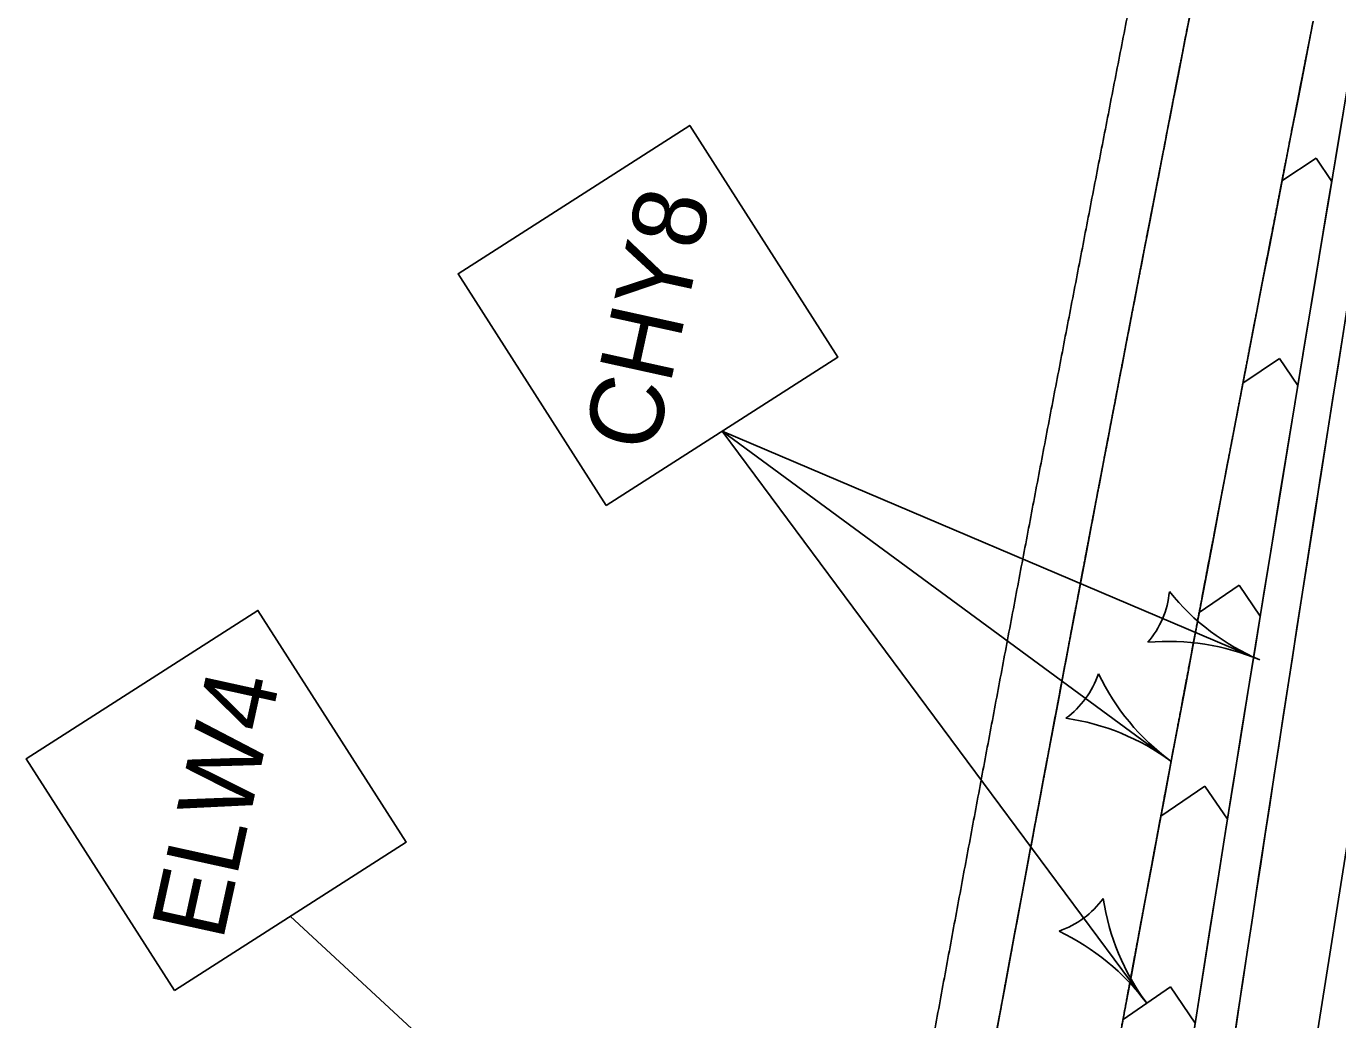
# Model space of a CAD drawing. Extents: x 14104283 to 14128447, y 8633203 to 8671666.
# Drawn here: x 14107883.7 to 14108012.5, y 8640340.4 to 8640438 of the extents above; entities that cross this region are included whole.
import ezdxf

# ---------------------------------------------------------------- set-up
doc = ezdxf.new("R2010")
doc.units = 0
for name, color, linetype in [('Default', 7, 'Continuous'), ('dsnPaintPlaceBrokenLineWhite', 7, 'Continuous'), ('dsnPaintPlaceChannelizingLaneWhite', 7, 'Continuous'), ('dsnPaintPlaceEdgeLineRightWhite', 7, 'Continuous'), ('dsnStdLabel', 7, 'Continuous'), ('dsnStgShadingPrevPav', 7, 'Continuous')]:
    doc.layers.add(name, color=color, linetype=linetype)

msp = doc.modelspace()

# ---------------------------------------------------------------- linework, layer by layer
at = {"layer": 'Default'}
for centre, radius, start, end in [((14117394.14, 8638857.08), 9512, 167.610212, 171.325989), ((14117394.14, 8638857.08), 9500, 167.610212, 171.325989), ((14117394.14, 8638857.08), 9500, 167.610212, 171.325989), ((14117350.61, 8638608.07), 9530.2, 168.915826, 170.320937), ((14117350.61, 8638608.07), 9518.2, 168.915826, 170.320937)]:
    msp.add_arc(centre, radius, start, end, dxfattribs=at)
at = {"layer": 'dsnPaintPlaceBrokenLineWhite'}
msp.add_arc((14117394.14, 8638857.08), 9500, 167.610212, 171.325989, dxfattribs=at)
at = {"layer": 'dsnPaintPlaceChannelizingLaneWhite'}
for p, q in [((14108006.99, 8640422.76), (14108010.34, 8640425.01)), ((14108011.88, 8640422.72), (14108010.34, 8640425.01)), ((14108003.16, 8640402.9), (14108006.75, 8640405.34)), ((14108008.56, 8640402.67), (14108006.75, 8640405.34)), ((14107998.87, 8640380.39), (14108002.8, 8640383.07)), ((14108004.86, 8640380.03), (14108002.78, 8640383.07)), ((14107995.1, 8640360.4), (14107999.42, 8640363.36)), ((14108001.65, 8640360.1), (14107999.42, 8640363.36)), ((14107991.39, 8640340.45), (14107996.03, 8640343.65)), ((14107998.47, 8640340.1), (14107996.03, 8640343.65))]:
    msp.add_line(p, q, dxfattribs=at)
for centre, radius, start, end in [((14117394.14, 8638857.08), 9512, 169.444425, 171.325989), ((14117350.61, 8638608.07), 9518.2, 168.915826, 170.320937)]:
    msp.add_arc(centre, radius, start, end, dxfattribs=at)
at = {"layer": 'dsnPaintPlaceEdgeLineRightWhite'}
msp.add_arc((14117350.61, 8638608.07), 9530.2, 168.915826, 170.320937, dxfattribs=at)
at = {"layer": 'dsnStdLabel'}
for p, q in [((14107952.01, 8640398.19), (14107996.08, 8640365.81)), ((14107952.01, 8640398.19), (14108004.82, 8640375.74)), ((14107952.01, 8640398.19), (14107993.71, 8640342.05)), ((14107909.59, 8640350.58), (14107971.39, 8640293.53))]:
    msp.add_line(p, q, dxfattribs=at)
for points in [[(14107940.63, 8640390.92), (14107963.38, 8640405.47), (14107948.83, 8640428.21), (14107926.08, 8640413.66)], [(14107898.22, 8640343.3), (14107920.97, 8640357.85), (14107906.42, 8640380.6), (14107883.67, 8640366.05)]]:
    msp.add_lwpolyline(points, close=True, dxfattribs=at)
for centre, radius, start, end in [((14107987.11, 8640383.26), 8.86, 319.2327, 354.7011), ((14108013.8, 8640396.86), 22.95, 218.8957, 246.967), ((14107995.84, 8640354.62), 22.95, 66.9669, 95.0381), ((14107980.57, 8640377.2), 8.86, 305.9579, 341.4263), ((14108009.67, 8640384.3), 22.95, 205.6209, 233.6922), ((14107982.49, 8640347.31), 22.95, 53.6921, 81.7633), ((14107982.23, 8640357.5), 8.86, 288.8714, 324.3398), ((14108012.13, 8640355.73), 22.95, 188.5344, 216.6057), ((14107975.28, 8640328.36), 22.95, 36.6055, 64.6768)]:
    msp.add_arc(centre, radius, start, end, dxfattribs=at)
at = {"layer": 'dsnStgShadingPrevPav'}
for radius, start, end in [(9488, 167.610212, 172.222077), (9512, 169.413861, 172.222077), (9488, 169.413861, 172.222077), (9512, 170.574102, 171.702544)]:
    msp.add_arc((14117407.82, 8638919.35), radius, start, end, dxfattribs=at)
for points, degree in [([(14108040.07, 8640670.33), (14108039.11, 8640666.01), (14108035.79, 8640651.03), (14108029.85, 8640623.7), (14108025.19, 8640602.04), (14108020.26, 8640578.84), (14108015.47, 8640556.04), (14108010.72, 8640533.12), (14108006.03, 8640510.22), (14108001.39, 8640487.29), (14107996.81, 8640464.36), (14107992.28, 8640441.41), (14107987.82, 8640418.46), (14107983.4, 8640395.49), (14107979.05, 8640372.51), (14107974.75, 8640349.53), (14107970.51, 8640326.51), (14107966.33, 8640303.59), (14107962.15, 8640280.24), (14107958.29, 8640258.43), (14107953.48, 8640230.88), (14107950.9, 8640215.75), (14107950.15, 8640211.39)], 2), ([(14107956.07, 8640210.37), (14107957.38, 8640218.06), (14107960.02, 8640233.43), (14107964.04, 8640256.47), (14107968.11, 8640279.5), (14107972.24, 8640302.51), (14107976.42, 8640325.52), (14107980.66, 8640348.51), (14107984.96, 8640371.49), (14107989.32, 8640394.46), (14107993.73, 8640417.41), (14107998.19, 8640440.35), (14108002.71, 8640463.28), (14108007.29, 8640486.2), (14108011.92, 8640509.1), (14108016.61, 8640531.99), (14108021.36, 8640554.87), (14108026.16, 8640577.73), (14108031.01, 8640600.58), (14108035.93, 8640623.41), (14108040.89, 8640646.24), (14108044.25, 8640661.44), (14108045.92, 8640669.04)], 3), ([(14108010.05, 8640438.44), (14108009.9, 8640437.67), (14108009.75, 8640436.91), (14108009.6, 8640436.15)], 2), ([(14108009.6, 8640436.15), (14108009.75, 8640436.91), (14108009.9, 8640437.67), (14108010.05, 8640438.44)], 2), ([(14107995.51, 8640426.59), (14107996.26, 8640430.41), (14107997, 8640434.24), (14107997.75, 8640438.06)], 2), ([(14108009.6, 8640436.15), (14108009.52, 8640435.76), (14108009.45, 8640435.38), (14108009.37, 8640435)], 2), ([(14108009.37, 8640435), (14108009.45, 8640435.38), (14108009.52, 8640435.76), (14108009.6, 8640436.15)], 2), ([(14108009.37, 8640435), (14108009.15, 8640433.86), (14108008.93, 8640432.71), (14108008.7, 8640431.56)], 2), ([(14108008.7, 8640431.56), (14108008.93, 8640432.71), (14108009.15, 8640433.86), (14108009.37, 8640435)], 2), ([(14108008.7, 8640431.56), (14108008.63, 8640431.18), (14108008.55, 8640430.8), (14108008.48, 8640430.42)], 2), ([(14108008.48, 8640430.42), (14108008.55, 8640430.8), (14108008.63, 8640431.18), (14108008.7, 8640431.56)], 2), ([(14108008.48, 8640430.42), (14108008.4, 8640430.04), (14108008.33, 8640429.65), (14108008.26, 8640429.27)], 2), ([(14108008.26, 8640429.27), (14108008.33, 8640429.65), (14108008.4, 8640430.04), (14108008.48, 8640430.42)], 2), ([(14108008.03, 8640428.13), (14108007.29, 8640424.31), (14108006.55, 8640420.49), (14108005.81, 8640416.67)], 2), ([(14108005.81, 8640416.67), (14108006.55, 8640420.49), (14108007.29, 8640424.31), (14108008.03, 8640428.13)], 2), ([(14108008.26, 8640429.27), (14108008.18, 8640428.89), (14108008.11, 8640428.51), (14108008.03, 8640428.13)], 2), ([(14108008.03, 8640428.13), (14108008.11, 8640428.51), (14108008.18, 8640428.89), (14108008.26, 8640429.27)], 2), ([(14107995.29, 8640425.44), (14107995.37, 8640425.82), (14107995.44, 8640426.21), (14107995.51, 8640426.59)], 2), ([(14107994.85, 8640423.15), (14107994.92, 8640423.53), (14107994.99, 8640423.91), (14107995.07, 8640424.29)], 2), ([(14107995.07, 8640424.29), (14107995.14, 8640424.68), (14107995.22, 8640425.06), (14107995.29, 8640425.44)], 2), ([(14107994.4, 8640420.85), (14107994.55, 8640421.62), (14107994.7, 8640422.38), (14107994.85, 8640423.15)], 2), ([(14107994.18, 8640419.7), (14107994.25, 8640420.09), (14107994.33, 8640420.47), (14107994.4, 8640420.85)], 2), ([(14107993.73, 8640417.41), (14107993.88, 8640418.17), (14107994.03, 8640418.94), (14107994.18, 8640419.7)], 2), ([(14107992.63, 8640411.67), (14107993, 8640413.58), (14107993.36, 8640415.5), (14107993.73, 8640417.41)], 2), ([(14108005.81, 8640416.67), (14108005.73, 8640416.29), (14108005.66, 8640415.91), (14108005.59, 8640415.52)], 2), ([(14108005.59, 8640415.52), (14108005.66, 8640415.91), (14108005.73, 8640416.29), (14108005.81, 8640416.67)], 2), ([(14108005.59, 8640415.52), (14108005.36, 8640414.38), (14108005.14, 8640413.23), (14108004.92, 8640412.09)], 2), ([(14108004.92, 8640412.09), (14108005.14, 8640413.23), (14108005.36, 8640414.38), (14108005.59, 8640415.52)], 2), ([(14107991.52, 8640405.93), (14107991.89, 8640407.85), (14107992.26, 8640409.76), (14107992.63, 8640411.67)], 2), ([(14108004.92, 8640412.09), (14108004.77, 8640411.32), (14108004.63, 8640410.56), (14108004.48, 8640409.79)], 2), ([(14108004.48, 8640409.79), (14108004.63, 8640410.56), (14108004.77, 8640411.32), (14108004.92, 8640412.09)], 2), ([(14108004.48, 8640409.79), (14108004.18, 8640408.27), (14108003.89, 8640406.74), (14108003.6, 8640405.21)], 2), ([(14108003.6, 8640405.21), (14108003.89, 8640406.74), (14108004.18, 8640408.27), (14108004.48, 8640409.79)], 2), ([(14107991.3, 8640404.79), (14107991.38, 8640405.17), (14107991.45, 8640405.55), (14107991.52, 8640405.93)], 2), ([(14108003.6, 8640405.21), (14108003.3, 8640403.68), (14108003.01, 8640402.15), (14108002.72, 8640400.62)], 2), ([(14108002.72, 8640400.62), (14108003.01, 8640402.15), (14108003.3, 8640403.68), (14108003.6, 8640405.21)], 2), ([(14107990.42, 8640400.19), (14107990.72, 8640401.73), (14107991.01, 8640403.26), (14107991.3, 8640404.79)], 2), ([(14107989.54, 8640395.6), (14107989.84, 8640397.13), (14107990.13, 8640398.66), (14107990.42, 8640400.19)], 2), ([(14108002.72, 8640400.62), (14108002.28, 8640398.33), (14108001.84, 8640396.04), (14108001.4, 8640393.74)], 2), ([(14108001.4, 8640393.74), (14108001.84, 8640396.04), (14108002.28, 8640398.33), (14108002.72, 8640400.62)], 2), ([(14107989.33, 8640394.45), (14107989.4, 8640394.84), (14107989.47, 8640395.22), (14107989.54, 8640395.6)], 2), ([(14107989.11, 8640393.31), (14107989.18, 8640393.69), (14107989.25, 8640394.07), (14107989.33, 8640394.45)], 2), ([(14108001.4, 8640393.74), (14108001.33, 8640393.36), (14108001.25, 8640392.98), (14108001.18, 8640392.6)], 2), ([(14108001.18, 8640392.6), (14108001.25, 8640392.98), (14108001.33, 8640393.36), (14108001.4, 8640393.74)], 2), ([(14107988.23, 8640388.71), (14107988.52, 8640390.25), (14107988.81, 8640391.78), (14107989.11, 8640393.31)], 2), ([(14108001.18, 8640392.6), (14108001.03, 8640391.83), (14108000.89, 8640391.07), (14108000.74, 8640390.3)], 2), ([(14108000.74, 8640390.3), (14108000.89, 8640391.07), (14108001.03, 8640391.83), (14108001.18, 8640392.6)], 2), ([(14108000.74, 8640390.3), (14108000.6, 8640389.54), (14108000.45, 8640388.78), (14108000.31, 8640388.01)], 2), ([(14108000.31, 8640388.01), (14108000.45, 8640388.78), (14108000.6, 8640389.54), (14108000.74, 8640390.3)], 2), ([(14107987.58, 8640385.27), (14107987.79, 8640386.42), (14107988.01, 8640387.57), (14107988.23, 8640388.71)], 2), ([(14108000.31, 8640388.01), (14108000.02, 8640386.48), (14107999.72, 8640384.95), (14107999.43, 8640383.42)], 2), ([(14107999.43, 8640383.42), (14107999.72, 8640384.95), (14108000.02, 8640386.48), (14108000.31, 8640388.01)], 2), ([(14107987.36, 8640384.12), (14107987.43, 8640384.5), (14107987.5, 8640384.89), (14107987.58, 8640385.27)], 2), ([(14107986.92, 8640381.82), (14107987.07, 8640382.59), (14107987.21, 8640383.36), (14107987.36, 8640384.12)], 2), ([(14107999.43, 8640383.42), (14107999, 8640381.13), (14107998.56, 8640378.84), (14107998.13, 8640376.54)], 2), ([(14107998.13, 8640376.54), (14107998.56, 8640378.84), (14107999, 8640381.13), (14107999.43, 8640383.42)], 2), ([(14107986.05, 8640377.23), (14107986.34, 8640378.76), (14107986.63, 8640380.29), (14107986.92, 8640381.82)], 2), ([(14107985.84, 8640376.08), (14107985.91, 8640376.46), (14107985.98, 8640376.85), (14107986.05, 8640377.23)], 2), ([(14107985.19, 8640372.64), (14107985.4, 8640373.78), (14107985.62, 8640374.93), (14107985.84, 8640376.08)], 2), ([(14107997.91, 8640375.4), (14107997.55, 8640373.48), (14107997.19, 8640371.57), (14107996.83, 8640369.66)], 2), ([(14107996.83, 8640369.66), (14107997.19, 8640371.57), (14107997.55, 8640373.48), (14107997.91, 8640375.4)], 2), ([(14107998.13, 8640376.54), (14107998.06, 8640376.16), (14107997.99, 8640375.78), (14107997.91, 8640375.4)], 2), ([(14107997.91, 8640375.4), (14107997.99, 8640375.78), (14107998.06, 8640376.16), (14107998.13, 8640376.54)], 2), ([(14107984.32, 8640368.04), (14107984.54, 8640369.19), (14107984.76, 8640370.34), (14107984.97, 8640371.49)], 2), ([(14107984.97, 8640371.49), (14107985.04, 8640371.87), (14107985.12, 8640372.25), (14107985.19, 8640372.64)], 2), ([(14107996.83, 8640369.66), (14107996.62, 8640368.51), (14107996.4, 8640367.37), (14107996.18, 8640366.22)], 2), ([(14107996.18, 8640366.22), (14107996.4, 8640367.37), (14107996.62, 8640368.51), (14107996.83, 8640369.66)], 2), ([(14107983.25, 8640362.3), (14107983.6, 8640364.21), (14107983.96, 8640366.13), (14107984.32, 8640368.04)], 2), ([(14107995.97, 8640365.07), (14107995.9, 8640364.69), (14107995.82, 8640364.31), (14107995.75, 8640363.92)], 2), ([(14107995.75, 8640363.92), (14107995.82, 8640364.31), (14107995.9, 8640364.69), (14107995.97, 8640365.07)], 2), ([(14107996.18, 8640366.22), (14107996.11, 8640365.84), (14107996.04, 8640365.45), (14107995.97, 8640365.07)], 2), ([(14107995.97, 8640365.07), (14107996.04, 8640365.45), (14107996.11, 8640365.84), (14107996.18, 8640366.22)], 2), ([(14107995.75, 8640363.92), (14107995.68, 8640363.54), (14107995.61, 8640363.16), (14107995.54, 8640362.78)], 2), ([(14107995.54, 8640362.78), (14107995.61, 8640363.16), (14107995.68, 8640363.54), (14107995.75, 8640363.92)], 2), ([(14107995.54, 8640362.78), (14107995.32, 8640361.63), (14107995.11, 8640360.48), (14107994.89, 8640359.33)], 2), ([(14107994.89, 8640359.33), (14107995.11, 8640360.48), (14107995.32, 8640361.63), (14107995.54, 8640362.78)], 2), ([(14107982.39, 8640357.7), (14107982.67, 8640359.23), (14107982.96, 8640360.76), (14107983.25, 8640362.3)], 2), ([(14107994.89, 8640359.33), (14107994.68, 8640358.19), (14107994.46, 8640357.04), (14107994.25, 8640355.89)], 2), ([(14107994.25, 8640355.89), (14107994.46, 8640357.04), (14107994.68, 8640358.19), (14107994.89, 8640359.33)], 2), ([(14107981.96, 8640355.4), (14107982.1, 8640356.17), (14107982.24, 8640356.93), (14107982.39, 8640357.7)], 2), ([(14107981.74, 8640354.25), (14107981.81, 8640354.64), (14107981.89, 8640355.02), (14107981.96, 8640355.4)], 2), ([(14107994.03, 8640354.74), (14107993.96, 8640354.36), (14107993.89, 8640353.98), (14107993.82, 8640353.6)], 2), ([(14107993.82, 8640353.6), (14107993.89, 8640353.98), (14107993.96, 8640354.36), (14107994.03, 8640354.74)], 2), ([(14107994.25, 8640355.89), (14107994.18, 8640355.51), (14107994.11, 8640355.13), (14107994.03, 8640354.74)], 2), ([(14107994.03, 8640354.74), (14107994.11, 8640355.13), (14107994.18, 8640355.51), (14107994.25, 8640355.89)], 2), ([(14107981.53, 8640353.1), (14107981.6, 8640353.49), (14107981.67, 8640353.87), (14107981.74, 8640354.25)], 2), ([(14107993.82, 8640353.6), (14107993.75, 8640353.21), (14107993.68, 8640352.83), (14107993.61, 8640352.45)], 2), ([(14107993.61, 8640352.45), (14107993.68, 8640352.83), (14107993.75, 8640353.21), (14107993.82, 8640353.6)], 2), ([(14107981.1, 8640350.81), (14107981.24, 8640351.57), (14107981.39, 8640352.34), (14107981.53, 8640353.1)], 2), ([(14107993.61, 8640352.45), (14107993.53, 8640352.06), (14107993.46, 8640351.68), (14107993.39, 8640351.3)], 2), ([(14107993.39, 8640351.3), (14107993.46, 8640351.68), (14107993.53, 8640352.06), (14107993.61, 8640352.45)], 2), ([(14107993.39, 8640351.3), (14107993.11, 8640349.77), (14107992.82, 8640348.24), (14107992.54, 8640346.71)], 2), ([(14107992.54, 8640346.71), (14107992.82, 8640348.24), (14107993.11, 8640349.77), (14107993.39, 8640351.3)], 2), ([(14107980.67, 8640348.51), (14107980.74, 8640348.89), (14107980.82, 8640349.27), (14107980.89, 8640349.66)], 2), ([(14107980.89, 8640349.66), (14107980.96, 8640350.04), (14107981.03, 8640350.42), (14107981.1, 8640350.81)], 2), ([(14107980.46, 8640347.36), (14107980.53, 8640347.74), (14107980.6, 8640348.12), (14107980.67, 8640348.51)], 2), ([(14107979.4, 8640341.61), (14107979.75, 8640343.53), (14107980.1, 8640345.44), (14107980.46, 8640347.36)], 2), ([(14107992.54, 8640346.71), (14107992.11, 8640344.41), (14107991.69, 8640342.12), (14107991.26, 8640339.82)], 2), ([(14107991.26, 8640339.82), (14107991.69, 8640342.12), (14107992.11, 8640344.41), (14107992.54, 8640346.71)], 2), ([(14107978.33, 8640335.86), (14107978.69, 8640337.78), (14107979.04, 8640339.7), (14107979.4, 8640341.61)], 2)]:
    msp.add_open_spline(points, degree=degree, dxfattribs=at)

# ---------------------------------------------------------------- texts
at = {"layer": 'dsnStdLabel'}
for s, p in [('CHY8', (14107945.42, 8640395.9)), ('ELW4', (14107902.95, 8640348.04))]:
    msp.add_text(s, height=7.2, rotation=77.6078, dxfattribs=at).set_placement(p)

doc.saveas('drawing.dxf')
